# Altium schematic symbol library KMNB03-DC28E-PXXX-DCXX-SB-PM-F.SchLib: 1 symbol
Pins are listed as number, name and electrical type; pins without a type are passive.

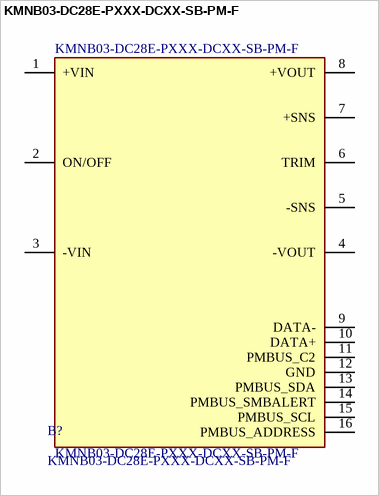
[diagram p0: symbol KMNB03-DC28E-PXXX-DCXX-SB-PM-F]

## KMNB03-DC28E-PXXX-DCXX-SB-PM-F
designator B?
9-40Vin XXVout XXXW Nonisolated Sixteenth Brick with Flanged Option; MFG: KOLT
footprint KMNB03-DC28E-PXXX-DCXX-SB-PM-F
pins: 1 +VIN, 2 ON/OFF, 3 -VIN, 4 -VOUT, 5 -SNS, 6 TRIM, 7 +SNS, 8 +VOUT, 9 DATA-, 10 DATA+, 11 PMBUS_C2, 12 GND, 13 PMBUS_SDA, 14 PMBUS_SMBALERT, 15 PMBUS_SCL, 16 PMBUS_ADDRESS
